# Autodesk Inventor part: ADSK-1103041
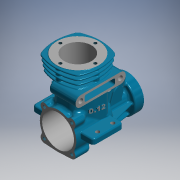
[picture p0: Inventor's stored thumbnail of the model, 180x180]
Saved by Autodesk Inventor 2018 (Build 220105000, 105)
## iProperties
Shininess: 11.0
Length Units: 11269
Angle Units: 11279
Time Units: 11290
Mass Units: 11286
Length Display Precision: 2
Angle Display Precision: 2
Compacted: True
Created: 2000-07
Part Number: ADSK-1103041
Document SubType Name: Modeling
Material: Cast Steel
Description: ENGINE CASE - SIDE
Mass: 109.721 g
Surface Area: 158.984 cm^2
Volume: 13.9772 cm^3
Density: 7.85 g/cm^3
Appearance: Sky Blue Dark
Density: 0.0
Volumn: 0.0
Area: 0.0
PropertySet Name: Model Information
Control State: 0
Master: False
Checked Out: False
Author: Autodesk, Inc.
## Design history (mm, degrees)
node "Extrusion1" dims "d2" = 3.5, "d3" = 0
  sketch "Sketch2"
    geometry: L1 (-28.715, -16.977)-(11.285, -16.977); L2 (11.285, -16.977)-(11.285, 3.023); L3 (11.285, 3.023)-(-28.715, 3.023); L4 (-28.715, 3.023)-(-28.715, -16.977)
    constraints: 8 end point, 2 parallel, 1 horizontal, 1 perpendicular
    dimensions: "d0" = 40 distance of L2.end L3.end; "d1" = 20 distance of L3.end L1.start
workplane "Work Plane1"
workplane "Work Plane2"
node "Extrusion2" dims "d6" = 3.5, "d7" = 0
  sketch "Sketch3"
    geometry: L1 (20, -16.8)-(20, 16.8) reference; L2 (0, 0)-(40, 0) reference; C1 r 12 at (20, 0)
    constraints: 1 centre point, 1 midpoint
    dimensions: "d5" = 24 diameter of C1
node "Extrusion3" dims "d13" = 25, "d14" = 0
  sketch "Sketch4"
    geometry: L1 (-20.715, 3.023)-(3.285, 3.023); L2 (-2.715, -16.977)-(-14.715, -16.977); L3 (-8.715, -21.506)-(-8.715, 7.111) reference; L4 (-28.715, -16.977)-(-20.715, -16.977) reference; A1 r 36.333 centre (-33.049, 3.023) between (-2.715, -16.977) and (3.285, 3.023); A2 r 36.333 centre (15.618, 3.023) between (-20.715, 3.023) and (-14.715, -16.977)
    constraints: 4 end point, 4 point on circle, 2 centre point, 2 point on line, 1 collinear, 1 horizontal
    dimensions: "d8" = 24 distance of L1.start L1.end; "d9" = 12 distance of L2.start L2.end; "d10" = 6 distance from line of L3 L2.start (= 0.5 x d9); "d11" = 12 distance from line of L1.end L3 (= 0.5 x d8); "d12" = 20 distance between parallel lines of L2 L1
node "Extrusion4" dims "d15" = 2.5, "d16" = -15 deg
  sketch "Sketch5"
    geometry: A1 r 12 centre (-20, 3.5) between (-8, 3.5) and (-32, 3.5) reference; 1 further point
    constraints: 1 coincident, 1 horizontal alignment, 2 other
node "Extrusion5" dims "d18" = 14, "d19" = 0
  sketch "Sketch6"
    geometry: C1 r 11.33 at (0, 0) reference; C2 r 7.5 at (0, 0)
    constraints: 1 centre point, 1 coincident
    dimensions: "d17" = 15 diameter of C2
node "Extrusion6" dims "d21" = 6, "d22" = 0
  sketch "Sketch7"
    geometry: C1 r 7.5 at (0, 0) reference; C2 r 11 at (0, 0)
    constraints: 1 centre point, 1 coincident
    dimensions: "d20" = 22 diameter of C2
node "Extrusion7" dims "d24" = 1, "d25" = 0
  sketch "Sketch9"
    geometry: L1 (20.715, 3.023)-(28.715, 3.023) reference; L2 (20.715, 3.023)-(8.217, 3.023); L3 (8.217, 3.023)-(8.217, 19.523); L4 (8.217, 19.523)-(19.715, 19.523); L5 (18.215, 19.523)-(22.637, 3.023); L6 (19.715, 19.523)-(19.715, 25.523) reference; L7 (20.715, 3.023)-(20.045, 5.523) reference
    constraints: 8 end point, 2 parallel, 2 point on line, 1 collinear, 1 perpendicular
    dimensions: "d23" = 1.5 distance from line of L5.start L6
node "Mirror1"
node "Revolution1" dims "d28" = 90 deg
  sketch "Sketch10"
    geometry: L1 (-20, -3.5)-(0, -3.5) reference; L2 (-21.176, 0.363)-(-25.964, 13.518); L3 (-22.5, -2.5)-(-22.5, 7.83) reference; L4 (-22.5, 4)-(-36.5, 4) reference; L5 (-25.964, 13.518)-(-32.307, 11.21); L6 (-42.5, -14.5)-(-42.5, 7.5) reference; L7 (-32.307, 11.21)-(-27.519, -1.946); L8 (-27.519, -1.946)-(-21.176, 0.363)
    constraints: 8 end point, 2 perpendicular, 2 point on line, 1 parallel
    dimensions: "d26" = 70 deg angle of L1 L2; "d27" = 13.5 diameter of L2 L7; "d231" = 14 distance of L2.start L2.end
node "Extrusion9" dims "d35" = 1, "d36" = 0
  sketch "Sketch12"
    geometry: L1 (-26.964, 12.518)-(-19, 12.518); L2 (-19, 12.518)-(-19, 3); L3 (-19, 3)-(-26.964, 3); L4 (-26.964, 3)-(-26.964, 12.518); L5 (-25.964, 13.518)-(-22.5, 4) reference; L6 (-22.5, -2.5)-(-22.5, 7.83) reference; L7 (-20, 0)-(-20, 25) reference
    constraints: 8 end point, 2 parallel, 1 horizontal, 1 perpendicular
    dimensions: "d31" = 1 distance between parallel lines of L7 L2; "d32" = 1 distance from line of L5.start L4; "d33" = 1 distance from line of L5.end L3; "d34" = 1 horizontal distance of L5.start L1.start
workplane "Work Plane3"
  workaxis "Work Axis1"
node "Extrusion10" dims "d40" = 1, "d41" = 0
  sketch "Sketch13"
    geometry: L1 (-23, -12)-(-25.5, -11.33) reference; L2 (-25.5, -11.33)-(-25.5, 8.012) reference; L3 (-39.5, -11)-(-39.5, 11) reference; L4 (-25.5, -7.5)-(-39.5, -7.5) reference; L5 (-23, -12)-(-39.5, -10); L6 (-39.5, -6.5)-(-23, -6.5); L7 (-23, -6.5)-(-23, -12); 3 further points
    constraints: 6 end point, 2 point on line, 1 parallel, 1 perpendicular
    dimensions: "d38" = 1 distance of L3.start L5.end; "d39" = 1 distance between parallel lines of L4 L6
node "Circular Pattern1" dims "d42" = 30, "d44" = 45 deg
workaxis "Work Axis2"
workplane "Work Plane4"
workplane "Work Plane5"
workpoint "Work Point1"
node "Extrusion11" dims "d47" = 1, "d48" = 0
  sketch "Sketch14"
    geometry: L1 (2.217, 13.646)-(2.581, 12.646) reference; L2 (-3.407, -0.873)-(4.042, -0.873); L3 (-13.419, 36.867)-(12.256, -33.673) reference; L4 (4.042, -0.873)-(1.423, 6.324); L5 (-5.155, 3.93)-(-3.407, -0.873); A1 r 3.5 centre (-1.866, 5.127) between (1.423, 6.324) and (-5.155, 3.93); 1 further point
    constraints: 6 end point, 2 parallel, 2 point on circle, 2 tangent, 1 centre point, 1 horizontal, 1 point on line
    dimensions: "d45" = 3.5 radius of A1; "d46" = 6 distance from line of A1.centre L2; "d232" = 1 distance from line of point (5.681, 0.127) L2
node "Extrusion12" dims "d54" = 8, "d55" = 0
  sketch "Sketch15"
    geometry: L1 (-9, 9)-(9, 9); L2 (9, 9)-(9, -9); L3 (9, -9)-(-9, -9); L4 (-9, -9)-(-9, 9); C1 r 12 at (0, 0) reference; C2 r 2.5 at (-9, 9); C3 r 2.5 at (9, 9); C4 r 2.5 at (9, -9); C5 r 2.5 at (-9, -9)
    constraints: 8 end point, 4 centre point, 4 coincident, 3 equal radius, 2 parallel, 2 perpendicular, 1 horizontal
    dimensions: "d50" = 18 distance of L2.end L3.end; "d51" = 9 distance from line of C1.centre L4 (= 0.5 x d50); "d52" = 9 distance from line of C1.centre L3 (= d51); "d53" = 5 diameter of C3
node "Extrusion13" dims "d56" = 8, "d57" = 0
  sketch "Sketch16"
    geometry: L1 (10.857, -11.496)-(19.314, -11.98); L2 (29.143, -11.496)-(20.686, -11.98); A1 r 2.5 centre (11, -9) between (10.039, -6.692) and (13.308, -9.961) reference; A2 r 12 centre (20, 0) between (13.308, -9.961) and (26.692, -9.961) reference; A3 r 2.5 centre (29, -9) between (26.692, -9.961) and (29.961, -6.692) reference
    constraints: 4 end point, 4 point on circle, 4 tangent
node "Fillet1" dims "d58" = 2.5
node "Fillet2" dims "d59" = 2
node "Fillet3" dims "d60" = 5
node "Fillet4" dims "d61" = 3
node "Fillet5" dims "d62" = 2
node "Revolution2" dims "d63" = 180 deg
  sketch "Sketch17"
    geometry: L1 (0.686, 11.98)-(9.143, 11.496) reference; L2 (9.143, 11.496)-(0.686, 11.98); L3 (0.686, 11.98)-(0.543, 9.484); L4 (0.543, 9.484)-(9, 9); L5 (9, 9)-(9.143, 11.496); L6 (9, 9)-(11.496, 8.857); A1 r 12 centre (0, 0) between (9.961, 6.692) and (0.686, 11.98) reference; A2 r 2.5 centre (9, 9) between (9.961, 6.692) and (9.143, 11.496) reference
    constraints: 10 end point, 3 equal length, 2 perpendicular, 2 tangent, 1 point on circle, 1 point on line
node "Mirror2"
node "Fillet6" dims "d64" = 2.5
node "Fillet7" dims "d65" = 2
node "Fillet8" dims "d66" = 3.5
node "Fillet9" dims "d67" = 2
node "Fillet10" dims "d68" = 1
node "Fillet11" dims "d69" = 1
node "Fillet12" dims "d70" = 0.5
node "Fillet13" dims "d71" = 0.45
node "Fillet15" dims "d73" = 1
node "Fillet16" dims "d74" = 0.5
node "Fillet17" dims "d75" = 2
node "Fillet18" dims "d76" = 1
node "Fillet19" dims "d77" = 0.5
node "Fillet20" dims "d78" = 0.5
node "Fillet21" dims "d79" = 1
node "Fillet22" dims "d80" = 0.5
node "Fillet23" dims "d81" = 0.5
node "Fillet24" dims "d82" = 1
node "Fillet25" dims "d83" = 0.5
node "Extrusion14" dims "d84" = 9, "d85" = 0
  sketch "Sketch18"
    geometry: L1 (-17.028, 3.023)-(-0.402, 3.023) reference; L2 (-8.715, -24.577)-(-8.715, 7.623) reference; C1 r 10.018 at (-8.715, -6.996); A1 r 36.333 centre (15.618, 3.023) between (-20.508, -0.85) and (-16.281, -14.371) reference
    constraints: 2 tangent, 1 centre point, 1 point on line
node "Extrusion15" dims "d90" = 1, "d91" = 0
  sketch "Sketch19"
    geometry: L1 (5.035, 6.754)-(-22.465, 6.754); L2 (-22.465, 6.754)-(-22.465, -20.746); L3 (-22.465, -20.746)-(5.035, -20.746); L4 (5.035, -20.746)-(5.035, 6.754); A1 r 10.018 centre (-8.715, -6.996) between (0.549, -10.81) and (-8.715, 3.023) reference; A2 r 27.5 centre (-22.465, -6.996) between (2.599, -18.31) and (2.599, 4.319); A3 r 27.5 centre (5.035, -6.996) between (-20.03, 4.319) and (-20.03, -18.31); A4 r 27.5 centre (-8.715, 6.754) between (-20.03, -18.31) and (2.599, -18.31); A5 r 27.5 centre (-8.715, -20.746) between (2.599, 4.319) and (-20.03, 4.319); A6 r 29.032 centre (-8.715, -20.746) between (-22.465, 4.823) and (-23.458, 4.264)
    constraints: 12 point on circle, 8 end point, 5 centre point, 3 midpoint, 3 tangent, 2 parallel, 2 perpendicular, 1 horizontal, 1 point on line
    dimensions: "d86" = 27.5 distance of L2.end L3.end; "d87" = 13.75 distance from line of L4 A1.centre (= 0.5 x d86); "d88" = 13.75 distance from line of L3 A1.centre (= d87); "d89" = 13.75 distance from line of L2 A4.centre (= d87)
node "Fillet26" dims "d92" = 2
workplane "Work Plane6"
node "Extrusion16" dims "d95" = 1, "d96" = 0
  sketch "Sketch20"
    geometry: A1 r 27.5 centre (-8.715, -20.746) between (1.847, 4.645) and (-19.278, 4.645) reference; A2 r 27.5 centre (5.035, -6.996) between (-20.356, 3.567) and (-20.356, -17.558) reference; A3 r 2 centre (-18.509, 2.798) between (-19.278, 4.645) and (-20.356, 3.567) reference; A4 r 2 centre (1.079, 2.798) between (2.925, 3.567) and (1.847, 4.645) reference; A5 r 27.5 centre (-22.465, -6.996) between (2.925, -17.558) and (2.925, 3.567) reference; A6 r 2 centre (1.079, -16.79) between (1.847, -18.636) and (2.925, -17.558) reference; A7 r 27.5 centre (-8.715, 6.754) between (-19.278, -18.636) and (1.847, -18.636) reference; A8 r 2 centre (-18.509, -16.79) between (-20.356, -17.558) and (-19.278, -18.636) reference; A9 r 28 centre (-8.715, -20.746) between (2.039, 5.107) and (-19.47, 5.107); A10 r 2.5 centre (1.079, 2.798) between (3.387, 3.759) and (2.039, 5.107); A11 r 28 centre (-22.465, -6.996) between (3.387, -17.75) and (3.387, 3.759); A12 r 2.5 centre (1.079, -16.79) between (2.039, -19.098) and (3.387, -17.75); A13 r 28 centre (-8.715, 6.754) between (-19.47, -19.098) and (2.039, -19.098); A14 r 2.5 centre (-18.509, -16.79) between (-20.818, -17.75) and (-19.47, -19.098); A15 r 28 centre (5.035, -6.996) between (-20.818, 3.759) and (-20.818, -17.75); A16 r 2.5 centre (-18.509, 2.798) between (-19.47, 5.107) and (-20.818, 3.759)
    constraints: 16 point on circle, 8 centre point, 7 other
    dimensions: "d94" = 0.5 radial gap between concentric circles of A9 A1
workplane "Work Plane7"
node "Extrusion17" dims "d99" = 1, "d100" = 0
  sketch "Sketch21"
    geometry: A1 r 28 centre (-8.715, -20.746) between (2.039, 5.107) and (-19.47, 5.107) reference; A2 r 28 centre (5.035, -6.996) between (-20.818, 3.759) and (-20.818, -17.75) reference; A3 r 2.5 centre (-18.509, -16.79) between (-20.818, -17.75) and (-19.47, -19.098) reference; A4 r 2.5 centre (-18.509, 2.798) between (-19.47, 5.107) and (-20.818, 3.759) reference; A5 r 28 centre (-8.715, 6.754) between (-19.47, -19.098) and (2.039, -19.098) reference; A6 r 2.5 centre (1.079, -16.79) between (2.039, -19.098) and (3.387, -17.75) reference; A7 r 28 centre (-22.465, -6.996) between (3.387, -17.75) and (3.387, 3.759) reference; A8 r 2.5 centre (1.079, 2.798) between (3.387, 3.759) and (2.039, 5.107) reference; A9 r 28.5 centre (-8.715, -20.746) between (2.231, 5.568) and (-19.662, 5.568); A10 r 3 centre (1.079, 2.798) between (3.849, 3.951) and (2.231, 5.568); A11 r 28.5 centre (-22.465, -6.996) between (3.849, -17.942) and (3.849, 3.951); A12 r 3 centre (1.079, -16.79) between (2.231, -19.56) and (3.849, -17.942); A13 r 28.5 centre (-8.715, 6.754) between (-19.662, -19.56) and (2.231, -19.56); A14 r 3 centre (-18.509, -16.79) between (-21.279, -17.942) and (-19.662, -19.56); A15 r 28.5 centre (5.035, -6.996) between (-21.279, 3.951) and (-21.279, -17.942); A16 r 3 centre (-18.509, 2.798) between (-19.662, 5.568) and (-21.279, 3.951)
    constraints: 16 point on circle, 8 centre point, 7 other
    dimensions: "d98" = 0.5 radial gap between concentric circles of A9 A1
workplane "Work Plane8"
node "Extrusion18" dims "d103" = 1, "d104" = 0
  sketch "Sketch22"
    geometry: A1 r 28.5 centre (-8.715, -20.746) between (2.231, 5.568) and (-19.662, 5.568) reference; A2 r 3 centre (-18.509, 2.798) between (-19.662, 5.568) and (-21.279, 3.951) reference; A3 r 28.5 centre (5.035, -6.996) between (-21.279, 3.951) and (-21.279, -17.942) reference; A4 r 3 centre (-18.509, -16.79) between (-21.279, -17.942) and (-19.662, -19.56) reference; A5 r 28.5 centre (-8.715, 6.754) between (-19.662, -19.56) and (2.231, -19.56) reference; A6 r 3 centre (1.079, -16.79) between (2.231, -19.56) and (3.849, -17.942) reference; A7 r 28.5 centre (-22.465, -6.996) between (3.849, -17.942) and (3.849, 3.951) reference; A8 r 3 centre (1.079, 2.798) between (3.849, 3.951) and (2.231, 5.568) reference; A9 r 29 centre (-8.715, -20.746) between (2.423, 6.03) and (-19.854, 6.03); A10 r 3.5 centre (1.079, 2.798) between (4.31, 4.143) and (2.423, 6.03); A11 r 29 centre (-22.465, -6.996) between (4.31, -18.134) and (4.31, 4.143); A12 r 3.5 centre (1.079, -16.79) between (2.423, -20.021) and (4.31, -18.134); A13 r 29 centre (-8.715, 6.754) between (-19.854, -20.021) and (2.423, -20.021); A14 r 3.5 centre (-18.509, -16.79) between (-21.741, -18.134) and (-19.854, -20.021); A15 r 29 centre (5.035, -6.996) between (-21.741, 4.143) and (-21.741, -18.134); A16 r 3.5 centre (-18.509, 2.798) between (-19.854, 6.03) and (-21.741, 4.143)
    constraints: 16 point on circle, 8 centre point, 7 other
    dimensions: "d102" = 0.5 radial gap between concentric circles of A9 A1
node "Extrusion19" dims "d108" = 1, "d109" = 0
  sketch "Sketch23" dims "d105" = 23
    geometry: L1 (-8.715, -31.799)-(-8.715, 35.076) reference; C1 r 10.018 at (-8.715, -6.996) reference; A1 r 2 centre (-8.715, 4.504) between (-6.717, 4.422) and (-10.714, 4.422); A2 r 2 centre (-4.719, 4.339) between (-6.717, 4.422) and (-5.384, 2.453); A3 r 2 centre (-12.712, 4.339) between (-12.047, 2.453) and (-10.714, 4.422); A4 r 10.018 centre (-8.715, -6.996) between (-5.384, 2.453) and (-12.047, 2.453); 1 further point
    constraints: 8 point on circle, 4 centre point, 4 tangent, 2 equal radius, 1 coincident, 1 concentric, 1 point on line, 1 vertical alignment, 2 other
    dimensions: "d106" = 4 diameter of A1; "d107" = 2 radius of A2
workaxis "Work Axis3"
node "Circular Pattern2" dims "d110" = 40, "d112" = 360 deg
node "Fillet27" dims "d113" = 0.5
node "Fillet28" dims "d114" = 0.5
workplane "Work Plane9"
workaxis "Work Axis4"
  workpoint "Work Point2"
  workpoint "Work Point3"
node "Extrusion20" dims "d119" = 17.5, "d120" = 0
  sketch "Sketch24"
    geometry: L1 (16.322, 24.5)-(-52.304, 24.5) reference; L2 (-9.982, -25.58)-(-9.982, 43.93) reference; L3 (3.018, 17.5)-(-22.982, 17.5); L4 (-22.982, 24.5)-(3.018, 24.5); A1 r 3.5 centre (-22.982, 21) between (-22.982, 24.5) and (-22.982, 17.5); A2 r 3.5 centre (3.018, 21) between (3.018, 17.5) and (3.018, 24.5)
    constraints: 4 end point, 4 point on circle, 4 tangent, 2 centre point, 1 collinear, 1 parallel, 1 perpendicular
    dimensions: "d116" = 26 distance of A1.centre A2.centre; "d117" = 13 distance from line of L2 A2.centre (= 0.5 x d116); "d118" = 3.5 radius of A1
node "Fillet29" dims "d121" = 0.5
node "Fillet30" dims "d122" = 1
node "Extrusion21" dims "d123" = 18, "d124" = 0
  sketch "Sketch25"
    geometry: L1 (24, 0)-(24, -2.921) reference; L2 (24, -1.216)-(24, -4.821); A1 r 3.5 centre (21, -3.018) between (17.5, -3.018) and (24.351, -4.028) reference; A2 r 3.5 centre (21, -3.018) between (24, -1.216) and (24, -4.821)
    constraints: 4 point on circle, 2 end point, 1 centre point, 1 coincident, 1 collinear, 1 point on line
node "Fillet31" dims "d125" = 2.5
node "Extrusion22" dims "d126" = 18, "d127" = 0
  sketch "Sketch26"
    geometry: L1 (24, 22.884)-(24, 20) reference; L2 (24, 21.179)-(24, 24.784); A1 r 2.5 centre (21, 22.982) between (23.394, 23.703) and (18.5, 22.982) reference; A2 r 3.5 centre (21, 22.982) between (24, 24.784) and (24, 21.179); A3 r 3.5 centre (21, 22.982) between (24.351, 23.991) and (17.5, 22.982) reference
    constraints: 2 end point, 2 point on circle, 1 centre point, 1 coincident, 1 collinear, 1 concentric, 1 point on line
node "Fillet32" dims "d128" = 2.5
node "Fillet33" dims "d129" = 0.5
node "Fillet34" dims "d130" = 0.45
node "Extrusion23" dims "d134" = 18, "d135" = 0
  sketch "Sketch27"
    geometry: L1 (12.518, 25.62)-(12.518, 20) reference; L2 (18.56, 20)-(6.19, 20) reference; L3 (17.5, 22.982)-(17.5, -3.018) reference; L4 (17.5, 21)-(12.518, 22.81); L5 (17.5, 21)-(17.5, 19); L6 (12.518, 19)-(17.5, 19); L7 (12.518, 19)-(12.518, 22.81)
    constraints: 8 end point, 2 point on line, 1 collinear, 1 midpoint, 1 perpendicular
    dimensions: "d131" = 1 distance from line of L2 L4.start; "d132" = 2.8101 distance of L1.start L4.end (derived); "d133" = 2 distance from line of L4.start L6
node "Fillet35" dims "d136" = 1
node "Fillet36" dims "d137" = 0.5
node "Fillet37" dims "d138" = 0.5
node "Hole1" dims "d139" = 2.013, "d140" = 4, "d141" = 2, "d142" = 60 deg, "d143" = 5, "d144" = 118 deg
  sketch "Sketch28"
    geometry: A1 r 2.5 centre (29, 9) between (30.967, 7.457) and (27.457, 10.967) reference; A2 r 2.5 centre (11, 9) between (12.543, 10.967) and (9.033, 7.457) reference; A3 r 2.5 centre (11, -9) between (8.939, -7.585) and (10.857, -11.496) reference; A4 r 2.5 centre (29, -9) between (29.143, -11.496) and (31.061, -7.585) reference
node "Hole2" dims "d145" = 3, "d146" = 4, "d147" = 2, "d148" = 60 deg, "d149" = 5, "d150" = 118 deg
  sketch "Sketch29"
    geometry: A1 r 2.5 centre (21, 22.982) between (23.394, 23.703) and (18.5, 22.982) reference; A2 r 2.5 centre (21, -3.018) between (18.5, -3.018) and (23.394, -3.739) reference
node "Extrusion24" dims "d152" = 25, "d153" = 0
  sketch "Sketch30"
    geometry: C1 r 9 at (-8.715, -6.996); A1 r 10.518 centre (-8.715, -6.996) between (-18.635, -10.493) and (-12.213, -16.915) reference
    constraints: 1 centre point, 1 coincident
    dimensions: "d151" = 18 diameter of C1
node "Extrusion25" dims "d154" = 0.25, "d155" = 0
  sketch "Sketch31"
    geometry: C1 r 9 at (-8.715, -6.996) reference; A1 r 28.5 centre (-8.715, 6.754) between (-19.662, -19.56) and (2.231, -19.56) reference; 1 further point
    constraints: 1 coincident, 1 vertical alignment, 2 other
node "Fillet38" dims "d156" = 0.5
node "Hole3" dims "d157" = 2.013, "d158" = 4, "d159" = 2, "d160" = 60 deg, "d161" = 8, "d162" = 118 deg, "d260" = 6
  sketch "Sketch32"
    geometry: A1 r 2.5 centre (-8.715, 4.504) between (-6.218, 4.401) and (-11.213, 4.401) reference; 2 further points
node "Circular Pattern3" dims "d163" = 40, "d165" = 360 deg
workplane "Work Plane10"
node "Extrusion26" dims "d172" = 1, "d173" = 0
  sketch "Sketch33"
    geometry: L1 (17.028, 3.023)-(11.715, 3.023) reference; L2 (20.526, -0.601)-(20.118, -12.124); L3 (18.88, -14.446)-(13.843, -16.581); L4 (15.654, -15.27)-(18.9, -13.894); A1 r 36.333 centre (-15.618, 3.023) between (16.281, -14.371) and (20.508, -0.85) reference; A2 r 3.5 centre (17.028, -0.477) between (20.508, -0.85) and (17.028, 3.023) reference; A3 r 5 centre (11.892, -11.977) between (11.892, -16.977) and (16.281, -14.371) reference; A4 r 2 centre (18.119, -12.053) between (18.9, -13.894) and (20.118, -12.124)
    constraints: 6 end point, 5 point on circle, 4 tangent, 1 centre point, 1 parallel
    dimensions: "d168" = 115 deg angle of L3 L2; "d169" = 87.9716 deg angle of L2 L1; "d170" = 2 radius of A4; "d171" = 0.5 distance between parallel lines of L3 L4
node "Fillet39" dims "d174" = 0.5
node "Fillet40" dims "d175" = 0.5
node "Rectangular Pattern1" dims "d176" = 40, "d178" = 3
node "Extrusion27" dims "d180" = 4, "d181" = 0
  sketch "Sketch34"
    geometry: C1 r 11 at (0, 0) reference; C2 r 8 at (0, 0)
    constraints: 1 centre point, 1 coincident
    dimensions: "d179" = 16 diameter of C2
node "Extrusion28" dims "d183" = 4, "d184" = 0
  sketch "Sketch35"
    geometry: C1 r 8 at (0, 0) reference; C2 r 6 at (0, 0)
    constraints: 1 centre point, 1 coincident
    dimensions: "d182" = 12 diameter of C2
node "Extrusion29" dims "d186" = 20, "d187" = 0
  sketch "Sketch36"
    geometry: C1 r 10.5 at (20, 0); A1 r 12 centre (20, 0) between (30.859, -5.106) and (30.749, 5.334) reference
    constraints: 1 centre point, 1 coincident
    dimensions: "d185" = 21 diameter of C1
node "Extrusion30" dims "d189" = 22, "d190" = 0
  sketch "Sketch37"
    geometry: C1 r 7 at (-8.715, -6.996); A1 r 13.75 centre (-8.715, -6.996) between (5.035, -6.996) and (-22.465, -6.996) reference
    constraints: 1 centre point, 1 coincident
    dimensions: "d188" = 14 diameter of C1
node "Extrusion31" dims "d192" = 5, "d193" = 0
  sketch "Sketch38"
    geometry: C1 r 10.5 at (0, 0) reference; C2 r 9.5 at (0, 0)
    constraints: 1 centre point, 1 coincident
    dimensions: "d191" = 19 diameter of C2
node "Extrusion32" dims "d201" = 16.5, "d202" = 0
  sketch "Sketch41"
    geometry: L1 (-17.5, 22.982)-(-17.5, -3.018) reference; L2 (-24.5, -3.018)-(-24.5, 22.982) reference; L3 (-23, 10.982)-(-19, 10.982); L4 (-19, 10.982)-(-19, -0.518); L5 (-19, -0.518)-(-23, -0.518); L6 (-23, -0.518)-(-23, 10.982); L7 (-34.25, 18.982)-(-9, 18.982) reference; L8 (-34.25, 0.982)-(-9, 0.982) reference; C1 r 1.5 at (-21, -3.018) reference
    constraints: 8 end point, 2 parallel, 1 horizontal, 1 perpendicular
    dimensions: "d199" = 1.5 distance between parallel lines of L2 L6; "d200" = 1.5 distance between parallel lines of L1 L4 (= d199); "d204" = 2.5 distance from line of L5 C1.centre; "d205" = 8 distance between parallel lines of L7 L3
node "Fillet42" dims "d206" = 1.63
node "Fillet41" dims "d203" = 1
node "Extrusion33" dims "d210" = 4, "d211" = 0
  sketch "Sketch42"
    geometry: L1 (6.056, -10.5)-(-8.814, -10.5) reference; L2 (6.056, 0)-(0, 0) reference; L3 (6.056, -17.5)-(-10.444, -17.5) reference; L4 (6.056, 15.5)-(-10.444, 15.5) reference; L5 (5.239, -17.5)-(-10.444, -17.5); L6 (-4.472, 8.5)-(6.056, 8.5); L7 (6.056, 0)-(6.056, 8.5); C1 r 9 at (-8.944, -1) reference; A1 r 10.5 centre (-8.944, -1) between (1.508, 0) and (-4.472, 8.5); 3 further points
    constraints: 7 end point, 4 coincident, 2 parallel, 2 point on circle, 2 point on line, 1 centre point, 1 perpendicular
    dimensions: "d207" = 7 distance between parallel lines of L5 L1 (derived); "d208" = 7 distance between parallel lines of L4 L6 (derived); "d209" = 1.5 radial gap between concentric circles of A1 C1
node "Fillet43" dims "d212" = 3
node "Fillet44" dims "d213" = 1
node "Fillet45" dims "d214" = 2
node "Fillet46" dims "d215" = 0.5
workplane "Work Plane13"
node "Extrusion34" dims "d219" = 13, "d220" = 0
  sketch "Sketch43"
    geometry: L1 (-10.366, 28.481)-(15.384, -42.268) reference; L2 (0.134, -0.368)-(6.712, 2.026); L3 (-7.406, 0.612)-(6.343, 2.309) reference; C1 r 2.75 at (6.712, 2.026); 1 further point
    constraints: 2 end point, 1 centre point, 1 coincident, 1 perpendicular, 1 point on line
    dimensions: "d216" = 7 distance of L2.start L2.end; "d217" = 3.5 distance between parallel lines of L2 L3; "d218" = 5.5 diameter of C1
node "Fillet47" dims "d221" = 0.5
node "Extrusion35" dims "d223" = 15, "d224" = 0
  sketch "Sketch44"
    geometry: C1 r 5.5 at (6.75, 7); A1 r 6.75 centre (6.75, 7) between (6.75, 0.25) and (6.75, 0.25) reference; A2 r 6.75 centre (6.75, 7) between (6.75, 0.25) and (6.75, 0.25) reference
    constraints: 1 centre point, 1 coincident
    dimensions: "d222" = 11 diameter of C1
node "Extrusion36" dims "d226" = 15, "d227" = 0
  sketch "Sketch45"
    geometry: C1 r 2.75 at (0, 0) reference; C2 r 2 at (0, 0)
    constraints: 1 centre point, 1 coincident
    dimensions: "d225" = 4 diameter of C2
node "Hole4" dims "d233" = 2.5, "d234" = 4, "d235" = 2, "d236" = 60 deg, "d237" = 8, "d238" = 118 deg
  sketch "Sketch46"
    geometry: C1 r 1.078 at (8.285, -11.027) reference; C2 r 1.078 at (8.285, -1.027) reference; C3 r 1.078 at (-25.715, -1.977) reference; C4 r 1.078 at (-25.715, -11.977) reference
fillet "Fillet48" dims "d240" = 1
fillet "Fillet49" dims "d241" = 1
fillet "Fillet51" dims "d243" = 0.5
sketch "Sketch49"
  geometry: L1 (6.9, 8.859)-(16.548, 8.859); L2 (16.548, 8.859)-(16.548, 5.238); L3 (16.548, 5.238)-(6.9, 5.238); L4 (6.9, 5.238)-(6.9, 8.859)
  constraints: 2 other
emboss "Emboss2" sketch "Sketch49" dims "d248" = 0.5, "d249" = 0
workplane "Work Plane14"
workplane "Work Plane15"
  workaxis "Work Axis5"
  workaxis "Work Axis6"
body "Solid1"
other parameters: "d4" = 3, "d37" = 45 deg, "d93" = 2, "d97" = 2, "d101" = 2, "d115" = -15, "d166" = 2, "d259" = 0, "d261" = 0
